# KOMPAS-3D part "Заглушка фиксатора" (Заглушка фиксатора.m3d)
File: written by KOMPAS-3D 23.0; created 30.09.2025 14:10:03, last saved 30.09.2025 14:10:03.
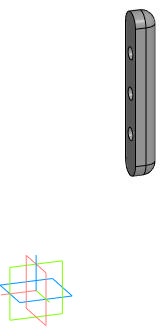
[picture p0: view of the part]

Document properties: Автор: Inspektor_Kot; Полное имя файла: I:\Autodesk Inventor Projects\ИМ-ИТ ЦД\Вариант 5\Заглушка фиксатора.m3d

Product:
- Part/product: Заглушка фиксатора
    Масса: 0.550024

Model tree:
1. Эскиз:1  (with: Элемент выдавливания:4, Элемент выдавливания:1, Скругление:1)
2. Элемент выдавливания:1
     Расстояние 1 = 10
3. Эскиз:2  (with: Элемент выдавливания:1)
4. Элемент выдавливания:2
     Расстояние 1 = 12.5
5. Скругление:1  (with: Элемент выдавливания:2)
     Радиус = 12.5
